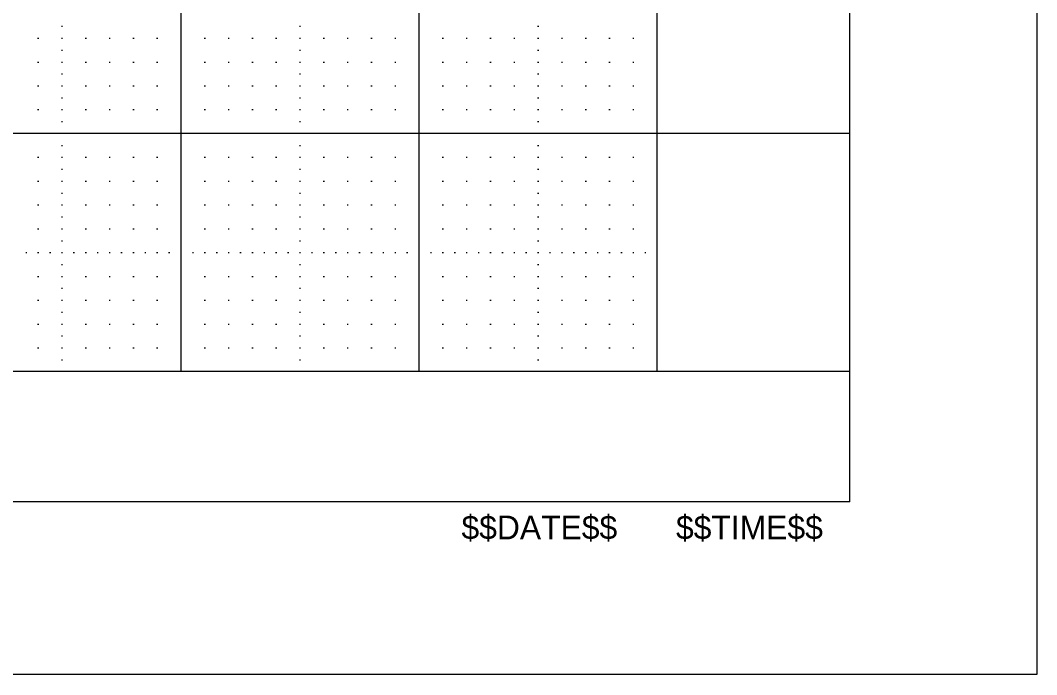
# Model space of a CAD drawing. Extents: x 0 to 34, y 0 to 22.
# Drawn here: x 29.731 to 34, y 0 to 2.747 of the extents above; entities that cross this region are included whole.
import ezdxf

# ---------------------------------------------------------------- set-up
doc = ezdxf.new("R2010")
doc.units = 0
for name, color, linetype in [('Level 1', 7, 'Continuous'), ('Level 4', 7, 'Continuous'), ('Level 48', 7, 'Continuous'), ('Level 5', 7, 'Continuous'), ('Level 63', 7, 'Continuous')]:
    doc.layers.add(name, color=color, linetype=linetype)

msp = doc.modelspace()

# ---------------------------------------------------------------- linework, layer by layer
at = {"layer": 'Level 1'}
for q in [(33.215, 21.272), (1.597, 0.726)]:
    msp.add_line((33.215, 0.726), q, dxfattribs=at)
at = {"layer": 'Level 4'}
for p, q in [((30.406, 1.272), (30.406, 20.272)), ((31.406, 1.272), (31.406, 20.272)), ((32.406, 1.272), (32.406, 20.272)), ((33.215, 2.272), (1.597, 2.272)), ((33.215, 1.272), (1.597, 1.272))]:
    msp.add_line(p, q, dxfattribs=at)
at = {"layer": 'Level 5'}
for p, q in [((29.9035, 2.7219), (29.9085, 2.7219)), ((30.9035, 2.7219), (30.9085, 2.7219)), ((31.9035, 2.7219), (31.9085, 2.7219)), ((29.8035, 2.6719), (29.8085, 2.6719)), ((29.9035, 2.6719), (29.9085, 2.6719)), ((30.0035, 2.6719), (30.0085, 2.6719)), ((30.1035, 2.6719), (30.1085, 2.6719)), ((30.2035, 2.6719), (30.2085, 2.6719)), ((30.3035, 2.6719), (30.3085, 2.6719)), ((30.5035, 2.6719), (30.5085, 2.6719)), ((30.6035, 2.6719), (30.6085, 2.6719)), ((30.7035, 2.6719), (30.7085, 2.6719)), ((30.8035, 2.6719), (30.8085, 2.6719)), ((30.9035, 2.6719), (30.9085, 2.6719)), ((31.0035, 2.6719), (31.0085, 2.6719)), ((31.1035, 2.6719), (31.1085, 2.6719)), ((31.2035, 2.6719), (31.2085, 2.6719)), ((31.3035, 2.6719), (31.3085, 2.6719)), ((31.5035, 2.6719), (31.5085, 2.6719)), ((31.6035, 2.6719), (31.6085, 2.6719)), ((31.7035, 2.6719), (31.7085, 2.6719)), ((31.8035, 2.6719), (31.8085, 2.6719)), ((31.9035, 2.6719), (31.9085, 2.6719)), ((32.0035, 2.6719), (32.0085, 2.6719)), ((32.1035, 2.6719), (32.1085, 2.6719)), ((32.2035, 2.6719), (32.2085, 2.6719)), ((32.3035, 2.6719), (32.3085, 2.6719)), ((29.9035, 2.6219), (29.9085, 2.6219)), ((30.9035, 2.6219), (30.9085, 2.6219)), ((31.9035, 2.6219), (31.9085, 2.6219)), ((29.8035, 2.5719), (29.8085, 2.5719)), ((29.9035, 2.5719), (29.9085, 2.5719)), ((30.0035, 2.5719), (30.0085, 2.5719)), ((30.1035, 2.5719), (30.1085, 2.5719)), ((30.2035, 2.5719), (30.2085, 2.5719)), ((30.3035, 2.5719), (30.3085, 2.5719)), ((30.5035, 2.5719), (30.5085, 2.5719)), ((30.6035, 2.5719), (30.6085, 2.5719)), ((30.7035, 2.5719), (30.7085, 2.5719)), ((30.8035, 2.5719), (30.8085, 2.5719)), ((30.9035, 2.5719), (30.9085, 2.5719)), ((31.0035, 2.5719), (31.0085, 2.5719)), ((31.1035, 2.5719), (31.1085, 2.5719)), ((31.2035, 2.5719), (31.2085, 2.5719)), ((31.3035, 2.5719), (31.3085, 2.5719)), ((31.5035, 2.5719), (31.5085, 2.5719)), ((31.6035, 2.5719), (31.6085, 2.5719)), ((31.7035, 2.5719), (31.7085, 2.5719)), ((31.8035, 2.5719), (31.8085, 2.5719)), ((31.9035, 2.5719), (31.9085, 2.5719)), ((32.0035, 2.5719), (32.0085, 2.5719)), ((32.1035, 2.5719), (32.1085, 2.5719)), ((32.2035, 2.5719), (32.2085, 2.5719)), ((32.3035, 2.5719), (32.3085, 2.5719)), ((29.9035, 2.5219), (29.9085, 2.5219)), ((30.9035, 2.5219), (30.9085, 2.5219)), ((31.9035, 2.5219), (31.9085, 2.5219)), ((29.8035, 2.4719), (29.8085, 2.4719)), ((29.9035, 2.4719), (29.9085, 2.4719)), ((30.0035, 2.4719), (30.0085, 2.4719)), ((30.1035, 2.4719), (30.1085, 2.4719)), ((30.2035, 2.4719), (30.2085, 2.4719)), ((30.3035, 2.4719), (30.3085, 2.4719)), ((30.5035, 2.4719), (30.5085, 2.4719)), ((30.6035, 2.4719), (30.6085, 2.4719)), ((30.7035, 2.4719), (30.7085, 2.4719)), ((30.8035, 2.4719), (30.8085, 2.4719)), ((30.9035, 2.4719), (30.9085, 2.4719)), ((31.0035, 2.4719), (31.0085, 2.4719)), ((31.1035, 2.4719), (31.1085, 2.4719)), ((31.2035, 2.4719), (31.2085, 2.4719)), ((31.3035, 2.4719), (31.3085, 2.4719)), ((31.5035, 2.4719), (31.5085, 2.4719)), ((31.6035, 2.4719), (31.6085, 2.4719)), ((31.7035, 2.4719), (31.7085, 2.4719)), ((31.8035, 2.4719), (31.8085, 2.4719)), ((31.9035, 2.4719), (31.9085, 2.4719)), ((32.0035, 2.4719), (32.0085, 2.4719)), ((32.1035, 2.4719), (32.1085, 2.4719)), ((32.2035, 2.4719), (32.2085, 2.4719)), ((32.3035, 2.4719), (32.3085, 2.4719)), ((29.9035, 2.4219), (29.9085, 2.4219)), ((30.9035, 2.4219), (30.9085, 2.4219)), ((31.9035, 2.4219), (31.9085, 2.4219)), ((29.8035, 2.3719), (29.8085, 2.3719)), ((29.9035, 2.3719), (29.9085, 2.3719)), ((30.0035, 2.3719), (30.0085, 2.3719)), ((30.1035, 2.3719), (30.1085, 2.3719)), ((30.2035, 2.3719), (30.2085, 2.3719)), ((30.3035, 2.3719), (30.3085, 2.3719)), ((30.5035, 2.3719), (30.5085, 2.3719)), ((30.6035, 2.3719), (30.6085, 2.3719)), ((30.7035, 2.3719), (30.7085, 2.3719)), ((30.8035, 2.3719), (30.8085, 2.3719)), ((30.9035, 2.3719), (30.9085, 2.3719)), ((31.0035, 2.3719), (31.0085, 2.3719)), ((31.1035, 2.3719), (31.1085, 2.3719)), ((31.2035, 2.3719), (31.2085, 2.3719)), ((31.3035, 2.3719), (31.3085, 2.3719)), ((31.5035, 2.3719), (31.5085, 2.3719)), ((31.6035, 2.3719), (31.6085, 2.3719)), ((31.7035, 2.3719), (31.7085, 2.3719)), ((31.8035, 2.3719), (31.8085, 2.3719)), ((31.9035, 2.3719), (31.9085, 2.3719)), ((32.0035, 2.3719), (32.0085, 2.3719)), ((32.1035, 2.3719), (32.1085, 2.3719)), ((32.2035, 2.3719), (32.2085, 2.3719)), ((32.3035, 2.3719), (32.3085, 2.3719)), ((29.9035, 2.3219), (29.9085, 2.3219)), ((30.9035, 2.3219), (30.9085, 2.3219)), ((31.9035, 2.3219), (31.9085, 2.3219)), ((29.9035, 2.2219), (29.9085, 2.2219)), ((30.9035, 2.2219), (30.9085, 2.2219)), ((31.9035, 2.2219), (31.9085, 2.2219)), ((29.8035, 2.1719), (29.8085, 2.1719)), ((29.9035, 2.1719), (29.9085, 2.1719)), ((30.0035, 2.1719), (30.0085, 2.1719)), ((30.1035, 2.1719), (30.1085, 2.1719)), ((30.2035, 2.1719), (30.2085, 2.1719)), ((30.3035, 2.1719), (30.3085, 2.1719)), ((30.5035, 2.1719), (30.5085, 2.1719)), ((30.6035, 2.1719), (30.6085, 2.1719)), ((30.7035, 2.1719), (30.7085, 2.1719)), ((30.8035, 2.1719), (30.8085, 2.1719)), ((30.9035, 2.1719), (30.9085, 2.1719)), ((31.0035, 2.1719), (31.0085, 2.1719)), ((31.1035, 2.1719), (31.1085, 2.1719)), ((31.2035, 2.1719), (31.2085, 2.1719)), ((31.3035, 2.1719), (31.3085, 2.1719)), ((31.5035, 2.1719), (31.5085, 2.1719)), ((31.6035, 2.1719), (31.6085, 2.1719)), ((31.7035, 2.1719), (31.7085, 2.1719)), ((31.8035, 2.1719), (31.8085, 2.1719)), ((31.9035, 2.1719), (31.9085, 2.1719)), ((32.0035, 2.1719), (32.0085, 2.1719)), ((32.1035, 2.1719), (32.1085, 2.1719)), ((32.2035, 2.1719), (32.2085, 2.1719)), ((32.3035, 2.1719), (32.3085, 2.1719)), ((29.9035, 2.1219), (29.9085, 2.1219)), ((30.9035, 2.1219), (30.9085, 2.1219)), ((31.9035, 2.1219), (31.9085, 2.1219)), ((29.8035, 2.0719), (29.8085, 2.0719)), ((29.9035, 2.0719), (29.9085, 2.0719)), ((30.0035, 2.0719), (30.0085, 2.0719)), ((30.1035, 2.0719), (30.1085, 2.0719)), ((30.2035, 2.0719), (30.2085, 2.0719)), ((30.3035, 2.0719), (30.3085, 2.0719)), ((30.5035, 2.0719), (30.5085, 2.0719)), ((30.6035, 2.0719), (30.6085, 2.0719)), ((30.7035, 2.0719), (30.7085, 2.0719)), ((30.8035, 2.0719), (30.8085, 2.0719)), ((30.9035, 2.0719), (30.9085, 2.0719)), ((31.0035, 2.0719), (31.0085, 2.0719)), ((31.1035, 2.0719), (31.1085, 2.0719)), ((31.2035, 2.0719), (31.2085, 2.0719)), ((31.3035, 2.0719), (31.3085, 2.0719)), ((31.5035, 2.0719), (31.5085, 2.0719)), ((31.6035, 2.0719), (31.6085, 2.0719)), ((31.7035, 2.0719), (31.7085, 2.0719)), ((31.8035, 2.0719), (31.8085, 2.0719)), ((31.9035, 2.0719), (31.9085, 2.0719)), ((32.0035, 2.0719), (32.0085, 2.0719)), ((32.1035, 2.0719), (32.1085, 2.0719)), ((32.2035, 2.0719), (32.2085, 2.0719)), ((32.3035, 2.0719), (32.3085, 2.0719)), ((29.9035, 2.0219), (29.9085, 2.0219)), ((30.9035, 2.0219), (30.9085, 2.0219)), ((31.9035, 2.0219), (31.9085, 2.0219)), ((29.8035, 1.9719), (29.8085, 1.9719)), ((29.9035, 1.9719), (29.9085, 1.9719)), ((30.0035, 1.9719), (30.0085, 1.9719)), ((30.1035, 1.9719), (30.1085, 1.9719)), ((30.2035, 1.9719), (30.2085, 1.9719)), ((30.3035, 1.9719), (30.3085, 1.9719)), ((30.5035, 1.9719), (30.5085, 1.9719)), ((30.6035, 1.9719), (30.6085, 1.9719)), ((30.7035, 1.9719), (30.7085, 1.9719)), ((30.8035, 1.9719), (30.8085, 1.9719)), ((30.9035, 1.9719), (30.9085, 1.9719)), ((31.0035, 1.9719), (31.0085, 1.9719)), ((31.1035, 1.9719), (31.1085, 1.9719)), ((31.2035, 1.9719), (31.2085, 1.9719)), ((31.3035, 1.9719), (31.3085, 1.9719)), ((31.5035, 1.9719), (31.5085, 1.9719)), ((31.6035, 1.9719), (31.6085, 1.9719)), ((31.7035, 1.9719), (31.7085, 1.9719)), ((31.8035, 1.9719), (31.8085, 1.9719)), ((31.9035, 1.9719), (31.9085, 1.9719)), ((32.0035, 1.9719), (32.0085, 1.9719)), ((32.1035, 1.9719), (32.1085, 1.9719)), ((32.2035, 1.9719), (32.2085, 1.9719)), ((32.3035, 1.9719), (32.3085, 1.9719)), ((29.9035, 1.9219), (29.9085, 1.9219)), ((30.9035, 1.9219), (30.9085, 1.9219)), ((31.9035, 1.9219), (31.9085, 1.9219)), ((29.8035, 1.8719), (29.8085, 1.8719)), ((29.9035, 1.8719), (29.9085, 1.8719)), ((30.0035, 1.8719), (30.0085, 1.8719)), ((30.1035, 1.8719), (30.1085, 1.8719)), ((30.2035, 1.8719), (30.2085, 1.8719)), ((30.3035, 1.8719), (30.3085, 1.8719)), ((30.5035, 1.8719), (30.5085, 1.8719)), ((30.6035, 1.8719), (30.6085, 1.8719)), ((30.7035, 1.8719), (30.7085, 1.8719)), ((30.8035, 1.8719), (30.8085, 1.8719)), ((30.9035, 1.8719), (30.9085, 1.8719)), ((31.0035, 1.8719), (31.0085, 1.8719)), ((31.1035, 1.8719), (31.1085, 1.8719)), ((31.2035, 1.8719), (31.2085, 1.8719)), ((31.3035, 1.8719), (31.3085, 1.8719)), ((31.5035, 1.8719), (31.5085, 1.8719)), ((31.6035, 1.8719), (31.6085, 1.8719)), ((31.7035, 1.8719), (31.7085, 1.8719)), ((31.8035, 1.8719), (31.8085, 1.8719)), ((31.9035, 1.8719), (31.9085, 1.8719)), ((32.0035, 1.8719), (32.0085, 1.8719)), ((32.1035, 1.8719), (32.1085, 1.8719)), ((32.2035, 1.8719), (32.2085, 1.8719)), ((32.3035, 1.8719), (32.3085, 1.8719)), ((29.9035, 1.8219), (29.9085, 1.8219)), ((30.9035, 1.8219), (30.9085, 1.8219)), ((31.9035, 1.8219), (31.9085, 1.8219)), ((29.7535, 1.7719), (29.7585, 1.7719)), ((29.8035, 1.7719), (29.8085, 1.7719)), ((29.8535, 1.7719), (29.8585, 1.7719)), ((29.9035, 1.7719), (29.9085, 1.7719)), ((29.9535, 1.7719), (29.9585, 1.7719)), ((30.0035, 1.7719), (30.0085, 1.7719)), ((30.0535, 1.7719), (30.0585, 1.7719)), ((30.1035, 1.7719), (30.1085, 1.7719)), ((30.1535, 1.7719), (30.1585, 1.7719)), ((30.2035, 1.7719), (30.2085, 1.7719)), ((30.2535, 1.7719), (30.2585, 1.7719)), ((30.3035, 1.7719), (30.3085, 1.7719)), ((30.3535, 1.7719), (30.3585, 1.7719)), ((30.4535, 1.7719), (30.4585, 1.7719)), ((30.5035, 1.7719), (30.5085, 1.7719)), ((30.5535, 1.7719), (30.5585, 1.7719)), ((30.6035, 1.7719), (30.6085, 1.7719)), ((30.6535, 1.7719), (30.6585, 1.7719)), ((30.7035, 1.7719), (30.7085, 1.7719)), ((30.7535, 1.7719), (30.7585, 1.7719)), ((30.8035, 1.7719), (30.8085, 1.7719)), ((30.8535, 1.7719), (30.8585, 1.7719)), ((30.9035, 1.7719), (30.9085, 1.7719)), ((30.9535, 1.7719), (30.9585, 1.7719)), ((31.0035, 1.7719), (31.0085, 1.7719)), ((31.0535, 1.7719), (31.0585, 1.7719)), ((31.1035, 1.7719), (31.1085, 1.7719)), ((31.1535, 1.7719), (31.1585, 1.7719)), ((31.2035, 1.7719), (31.2085, 1.7719)), ((31.2535, 1.7719), (31.2585, 1.7719)), ((31.3035, 1.7719), (31.3085, 1.7719)), ((31.3535, 1.7719), (31.3585, 1.7719)), ((31.4535, 1.7719), (31.4585, 1.7719)), ((31.5035, 1.7719), (31.5085, 1.7719)), ((31.5535, 1.7719), (31.5585, 1.7719)), ((31.6035, 1.7719), (31.6085, 1.7719)), ((31.6535, 1.7719), (31.6585, 1.7719)), ((31.7035, 1.7719), (31.7085, 1.7719)), ((31.7535, 1.7719), (31.7585, 1.7719)), ((31.8035, 1.7719), (31.8085, 1.7719)), ((31.8535, 1.7719), (31.8585, 1.7719)), ((31.9035, 1.7719), (31.9085, 1.7719)), ((31.9535, 1.7719), (31.9585, 1.7719)), ((32.0035, 1.7719), (32.0085, 1.7719)), ((32.0535, 1.7719), (32.0585, 1.7719)), ((32.1035, 1.7719), (32.1085, 1.7719)), ((32.1535, 1.7719), (32.1585, 1.7719)), ((32.2035, 1.7719), (32.2085, 1.7719)), ((32.2535, 1.7719), (32.2585, 1.7719)), ((32.3035, 1.7719), (32.3085, 1.7719)), ((32.3535, 1.7719), (32.3585, 1.7719)), ((29.9035, 1.7219), (29.9085, 1.7219)), ((30.9035, 1.7219), (30.9085, 1.7219)), ((31.9035, 1.7219), (31.9085, 1.7219)), ((29.8035, 1.6719), (29.8085, 1.6719)), ((29.9035, 1.6719), (29.9085, 1.6719)), ((30.0035, 1.6719), (30.0085, 1.6719)), ((30.1035, 1.6719), (30.1085, 1.6719)), ((30.2035, 1.6719), (30.2085, 1.6719)), ((30.3035, 1.6719), (30.3085, 1.6719)), ((30.5035, 1.6719), (30.5085, 1.6719)), ((30.6035, 1.6719), (30.6085, 1.6719)), ((30.7035, 1.6719), (30.7085, 1.6719)), ((30.8035, 1.6719), (30.8085, 1.6719)), ((30.9035, 1.6719), (30.9085, 1.6719)), ((31.0035, 1.6719), (31.0085, 1.6719)), ((31.1035, 1.6719), (31.1085, 1.6719)), ((31.2035, 1.6719), (31.2085, 1.6719)), ((31.3035, 1.6719), (31.3085, 1.6719)), ((31.5035, 1.6719), (31.5085, 1.6719)), ((31.6035, 1.6719), (31.6085, 1.6719)), ((31.7035, 1.6719), (31.7085, 1.6719)), ((31.8035, 1.6719), (31.8085, 1.6719)), ((31.9035, 1.6719), (31.9085, 1.6719)), ((32.0035, 1.6719), (32.0085, 1.6719)), ((32.1035, 1.6719), (32.1085, 1.6719)), ((32.2035, 1.6719), (32.2085, 1.6719)), ((32.3035, 1.6719), (32.3085, 1.6719)), ((29.9035, 1.6219), (29.9085, 1.6219)), ((30.9035, 1.6219), (30.9085, 1.6219)), ((31.9035, 1.6219), (31.9085, 1.6219)), ((29.8035, 1.5719), (29.8085, 1.5719)), ((29.9035, 1.5719), (29.9085, 1.5719)), ((30.0035, 1.5719), (30.0085, 1.5719)), ((30.1035, 1.5719), (30.1085, 1.5719)), ((30.2035, 1.5719), (30.2085, 1.5719)), ((30.3035, 1.5719), (30.3085, 1.5719)), ((30.5035, 1.5719), (30.5085, 1.5719)), ((30.6035, 1.5719), (30.6085, 1.5719)), ((30.7035, 1.5719), (30.7085, 1.5719)), ((30.8035, 1.5719), (30.8085, 1.5719)), ((30.9035, 1.5719), (30.9085, 1.5719)), ((31.0035, 1.5719), (31.0085, 1.5719)), ((31.1035, 1.5719), (31.1085, 1.5719)), ((31.2035, 1.5719), (31.2085, 1.5719)), ((31.3035, 1.5719), (31.3085, 1.5719)), ((31.5035, 1.5719), (31.5085, 1.5719)), ((31.6035, 1.5719), (31.6085, 1.5719)), ((31.7035, 1.5719), (31.7085, 1.5719)), ((31.8035, 1.5719), (31.8085, 1.5719)), ((31.9035, 1.5719), (31.9085, 1.5719)), ((32.0035, 1.5719), (32.0085, 1.5719)), ((32.1035, 1.5719), (32.1085, 1.5719)), ((32.2035, 1.5719), (32.2085, 1.5719)), ((32.3035, 1.5719), (32.3085, 1.5719)), ((29.9035, 1.5219), (29.9085, 1.5219)), ((30.9035, 1.5219), (30.9085, 1.5219)), ((31.9035, 1.5219), (31.9085, 1.5219)), ((29.8035, 1.4719), (29.8085, 1.4719)), ((29.9035, 1.4719), (29.9085, 1.4719)), ((30.0035, 1.4719), (30.0085, 1.4719)), ((30.1035, 1.4719), (30.1085, 1.4719)), ((30.2035, 1.4719), (30.2085, 1.4719)), ((30.3035, 1.4719), (30.3085, 1.4719)), ((30.5035, 1.4719), (30.5085, 1.4719)), ((30.6035, 1.4719), (30.6085, 1.4719)), ((30.7035, 1.4719), (30.7085, 1.4719)), ((30.8035, 1.4719), (30.8085, 1.4719)), ((30.9035, 1.4719), (30.9085, 1.4719)), ((31.0035, 1.4719), (31.0085, 1.4719)), ((31.1035, 1.4719), (31.1085, 1.4719)), ((31.2035, 1.4719), (31.2085, 1.4719)), ((31.3035, 1.4719), (31.3085, 1.4719)), ((31.5035, 1.4719), (31.5085, 1.4719)), ((31.6035, 1.4719), (31.6085, 1.4719)), ((31.7035, 1.4719), (31.7085, 1.4719)), ((31.8035, 1.4719), (31.8085, 1.4719)), ((31.9035, 1.4719), (31.9085, 1.4719)), ((32.0035, 1.4719), (32.0085, 1.4719)), ((32.1035, 1.4719), (32.1085, 1.4719)), ((32.2035, 1.4719), (32.2085, 1.4719)), ((32.3035, 1.4719), (32.3085, 1.4719)), ((29.9035, 1.4219), (29.9085, 1.4219)), ((30.9035, 1.4219), (30.9085, 1.4219)), ((31.9035, 1.4219), (31.9085, 1.4219)), ((29.8035, 1.3719), (29.8085, 1.3719)), ((29.9035, 1.3719), (29.9085, 1.3719)), ((30.0035, 1.3719), (30.0085, 1.3719)), ((30.1035, 1.3719), (30.1085, 1.3719)), ((30.2035, 1.3719), (30.2085, 1.3719)), ((30.3035, 1.3719), (30.3085, 1.3719)), ((30.5035, 1.3719), (30.5085, 1.3719)), ((30.6035, 1.3719), (30.6085, 1.3719)), ((30.7035, 1.3719), (30.7085, 1.3719)), ((30.8035, 1.3719), (30.8085, 1.3719)), ((30.9035, 1.3719), (30.9085, 1.3719)), ((31.0035, 1.3719), (31.0085, 1.3719)), ((31.1035, 1.3719), (31.1085, 1.3719)), ((31.2035, 1.3719), (31.2085, 1.3719)), ((31.3035, 1.3719), (31.3085, 1.3719)), ((31.5035, 1.3719), (31.5085, 1.3719)), ((31.6035, 1.3719), (31.6085, 1.3719)), ((31.7035, 1.3719), (31.7085, 1.3719)), ((31.8035, 1.3719), (31.8085, 1.3719)), ((31.9035, 1.3719), (31.9085, 1.3719)), ((32.0035, 1.3719), (32.0085, 1.3719)), ((32.1035, 1.3719), (32.1085, 1.3719)), ((32.2035, 1.3719), (32.2085, 1.3719)), ((32.3035, 1.3719), (32.3085, 1.3719)), ((29.9035, 1.3219), (29.9085, 1.3219)), ((30.9035, 1.3219), (30.9085, 1.3219)), ((31.9035, 1.3219), (31.9085, 1.3219))]:
    msp.add_line(p, q, dxfattribs=at)
at = {"layer": 'Level 63'}
msp.add_lwpolyline([(0, 22), (34, 22), (34, 0), (0, 0)], close=True, dxfattribs=at)

# ---------------------------------------------------------------- texts
at = {"layer": 'Level 48'}
for s, p in [('$$DATE$$', (31.584, 0.568)), ('$$TIME$$', (32.485, 0.568))]:
    msp.add_text(s, height=0.1, dxfattribs=at).set_placement(p)

doc.saveas('drawing.dxf')
